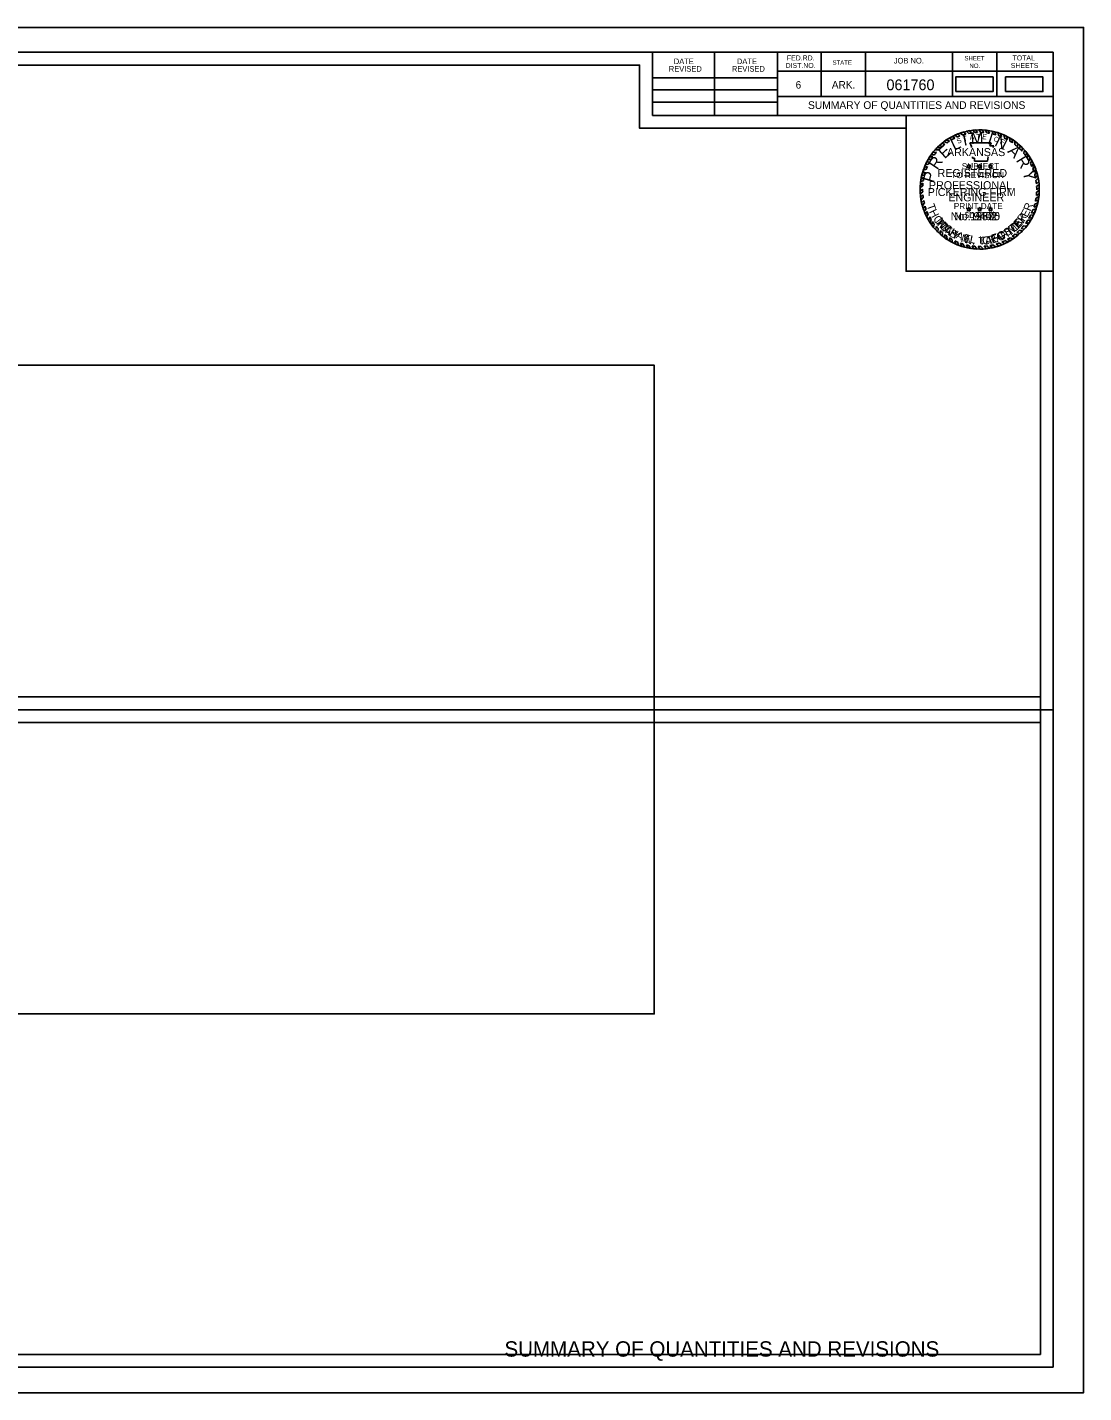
# Model space of a CAD drawing. Extents: x 365 to 1553, y -4 to 209.
# Drawn here: x 1387.5 to 1552.6, y -4 to 209.4 of the extents above; entities that cross this region are included whole.
import ezdxf

# ---------------------------------------------------------------- set-up
doc = ezdxf.new("R2010")
doc.units = 0
for name, color, linetype in [('Default', 7, 'Continuous'), ('R_Border', 7, 'Continuous'), ('R_Border Notes', 7, 'Continuous'), ('R_Border Plan-Plan', 7, 'Continuous'), ('R_Border Title', 7, 'Continuous'), ('R_No Plot', 7, 'Continuous'), ('STAMP_PE_CRAFTON', 7, 'Continuous'), ('STAMP_PE_FOSTER', 7, 'Continuous'), ('STAMP_PE_SEAL-INFO', 7, 'Continuous'), ('STAMP_PE_TAEGTMEYER', 7, 'Continuous'), ('STAMP_PE_TXT', 7, 'Continuous'), ('STAMP_PRELIMINARY', 7, 'Continuous')]:
    doc.layers.add(name, color=color, linetype=linetype)

msp = doc.modelspace()

# ---------------------------------------------------------------- linework, layer by layer
at = {"layer": 'Default'}
for points in [[(1532.59, 199.3), (1538.42, 199.3), (1538.42, 201.61), (1532.59, 201.61)], [(1540.36, 199.3), (1546.19, 199.3), (1546.19, 201.61), (1540.36, 201.61)], [(1315.56, 55.2), (1485.46, 55.2), (1485.46, 156.55), (1315.56, 156.55)]]:
    msp.add_lwpolyline(points, close=True, dxfattribs=at)
at = {"layer": 'R_Border'}
for p, q in [((1231.64, 205.46), (1547.82, 205.46)), ((1485.18, 195.58), (1485.18, 205.46)), ((1494.86, 195.58), (1494.86, 205.46)), ((1504.72, 205.46), (1504.72, 195.58)), ((1511.56, 205.46), (1511.56, 198.52)), ((1518.5, 205.46), (1518.5, 198.52)), ((1532.08, 205.46), (1532.08, 198.52)), ((1539.02, 205.46), (1539.02, 198.52)), ((1547.82, 0), (1547.82, 205.46)), ((1485.18, 201.44), (1504.72, 201.44)), ((1547.82, 202.52), (1504.72, 202.52)), ((1547.82, 202.54), (1547.82, 202.54)), ((1485.18, 199.58), (1504.72, 199.58)), ((1547.82, 198.52), (1504.72, 198.52)), ((1507.68, 198.52), (1547.82, 198.52)), ((1485.18, 197.64), (1504.72, 197.64)), ((1547.82, 195.58), (1485.18, 195.58)), ((1547.82, 0), (1231.64, 0))]:
    msp.add_line(p, q, dxfattribs=at)
at = {"layer": 'R_Border Plan-Plan'}
msp.add_line((1231.64, 102.73), (1547.82, 102.73), dxfattribs=at)
at = {"layer": 'R_No Plot'}
for points in [[(1219.23, 209.35), (1552.57, 209.35), (1552.57, -3.98), (1219.23, -3.98)], [(1545.82, 104.73), (1233.64, 104.73), (1233.64, 203.46), (1483.18, 203.46), (1483.18, 193.58), (1500.72, 193.58), (1524.82, 193.58), (1524.82, 171.25), (1545.82, 171.25)], [(1233.64, 203.46), (1483.18, 203.46), (1483.18, 193.58), (1500.72, 193.58), (1524.82, 193.58), (1524.82, 171.25), (1545.82, 171.25), (1545.82, 2), (1233.64, 2)], [(1524.82, 195.58), (1547.82, 195.58), (1547.82, 171.25), (1524.82, 171.25)], [(1233.64, 100.73), (1545.82, 100.73), (1545.82, 2), (1233.64, 2)]]:
    msp.add_lwpolyline(points, close=True, dxfattribs=at)
at = {"layer": 'STAMP_PE_SEAL-INFO'}
for p, q in [((1531.55, 192.03), (1531.98, 191.81)), ((1532, 192.28), (1532.46, 192.06)), ((1532.43, 192.49), (1532.82, 192.22)), ((1532.93, 192.71), (1533.23, 192.38)), ((1533.28, 192.84), (1533.66, 192.53)), ((1533.87, 193.02), (1534.16, 192.67)), ((1534.26, 193.11), (1534.62, 192.77)), ((1534.74, 193.21), (1535.04, 192.84)), ((1535.26, 193.28), (1535.54, 192.9)), ((1535.99, 192.93), (1535.68, 193.32)), ((1536.49, 192.93), (1536.21, 193.34)), ((1536.95, 192.91), (1536.69, 193.34)), ((1537.46, 192.86), (1537.16, 193.31)), ((1537.88, 192.8), (1537.62, 193.25)), ((1538.44, 192.68), (1538.27, 193.14)), ((1538.85, 192.57), (1538.69, 193.04)), ((1539.3, 192.42), (1539.16, 192.9)), ((1539.72, 192.26), (1539.57, 192.76)), ((1540.18, 192.06), (1540.07, 192.56)), ((1540.62, 191.83), (1540.54, 192.34)), ((1541.01, 191.6), (1540.97, 192.1)), ((1529.36, 190.22), (1529.88, 190.19)), ((1529.68, 190.57), (1530.23, 190.53)), ((1530.02, 190.89), (1530.48, 190.75)), ((1530.36, 191.19), (1530.89, 191.09)), ((1530.74, 191.52), (1531.2, 191.31)), ((1531.16, 191.79), (1531.6, 191.58)), ((1534.8, 191.31), (1538.14, 191.31)), ((1534.92, 191.01), (1534.8, 191.31)), ((1535.02, 190.71), (1534.92, 191.01)), ((1535.03, 190.59), (1535.02, 190.71)), ((1538.14, 191.31), (1537.91, 190.82)), ((1537.91, 190.82), (1538.55, 190.82)), ((1538.55, 190.82), (1538.4, 190.59)), ((1541.44, 191.32), (1541.41, 191.83)), ((1541.81, 191.05), (1541.84, 191.54)), ((1542.25, 190.68), (1542.27, 191.2)), ((1542.56, 190.39), (1542.63, 190.88)), ((1542.92, 190.01), (1542.99, 190.54)), ((1543.2, 189.7), (1543.33, 190.17)), ((1527.84, 187.89), (1528.34, 187.99)), ((1528.03, 188.27), (1528.52, 188.34)), ((1528.26, 188.7), (1528.75, 188.72)), ((1528.5, 189.1), (1529.02, 189.13)), ((1528.74, 189.44), (1529.24, 189.44)), ((1529.02, 189.81), (1529.56, 189.83)), ((1535.22, 188.89), (1535.19, 189.1)), ((1535.53, 188.89), (1535.22, 188.89)), ((1535.53, 188.46), (1535.53, 188.89)), ((1537.56, 188.46), (1535.53, 188.46)), ((1537.58, 188.79), (1537.56, 188.46)), ((1537.66, 189.1), (1537.58, 188.79)), ((1543.52, 189.28), (1543.66, 189.78)), ((1543.74, 188.96), (1543.92, 189.43)), ((1544.05, 188.47), (1544.23, 188.96)), ((1544.25, 188.1), (1544.48, 188.54)), ((1544.48, 187.62), (1544.71, 188.1)), ((1527.61, 185.89), (1527.14, 185.64)), ((1527.24, 186.14), (1527.71, 186.33)), ((1527.35, 186.54), (1527.82, 186.71)), ((1527.5, 187.05), (1527.99, 187.18)), ((1527.65, 187.45), (1528.16, 187.6)), ((1544.62, 187.28), (1544.88, 187.71)), ((1544.81, 186.73), (1545.09, 187.2)), ((1544.92, 186.37), (1545.22, 186.82)), ((1545.06, 185.81), (1545.37, 186.25)), ((1545.12, 185.43), (1545.48, 185.78)), ((1527.43, 184.57), (1527, 184.31)), ((1527.41, 184.08), (1527, 183.74)), ((1527.42, 183.67), (1527.02, 183.35)), ((1527.46, 185), (1527.03, 184.71)), ((1527.52, 185.43), (1527.08, 185.21)), ((1545.19, 184.92), (1545.56, 185.25)), ((1545.22, 184.5), (1545.61, 184.79)), ((1545.22, 183.58), (1545.64, 183.85)), ((1545.24, 183.98), (1545.64, 184.3)), ((1527.45, 183.18), (1527.08, 182.82)), ((1527.5, 182.75), (1527.15, 182.37)), ((1527.58, 182.29), (1527.24, 181.92)), ((1527.67, 181.87), (1527.36, 181.45)), ((1527.8, 181.42), (1527.5, 181)), ((1544.79, 181.24), (1545.28, 181.44)), ((1544.94, 181.73), (1545.41, 181.93)), ((1545.04, 182.18), (1545.5, 182.38)), ((1545.13, 182.68), (1545.58, 182.9)), ((1545.18, 183.07), (1545.62, 183.33)), ((1527.94, 181), (1527.66, 180.59)), ((1528.1, 180.57), (1527.84, 180.15)), ((1528.28, 180.19), (1528.05, 179.73)), ((1528.51, 179.73), (1528.32, 179.24)), ((1528.75, 179.33), (1528.56, 178.86)), ((1543.84, 179.23), (1544.31, 179.22)), ((1544.01, 179.51), (1544.51, 179.56)), ((1544.28, 180), (1544.77, 180.07)), ((1544.44, 180.34), (1544.93, 180.44)), ((1544.65, 180.86), (1545.14, 180.99)), ((1528.95, 179.01), (1528.84, 178.46)), ((1529.23, 178.62), (1529.13, 178.09)), ((1529.53, 178.25), (1529.45, 177.73)), ((1529.84, 177.91), (1529.77, 177.39)), ((1530.16, 177.58), (1530.13, 177.05)), ((1530.5, 177.27), (1530.5, 176.74)), ((1542.14, 177.27), (1542.61, 177.14)), ((1542.55, 177.64), (1542.99, 177.51)), ((1542.8, 177.9), (1543.28, 177.82)), ((1543.19, 178.34), (1543.65, 178.26)), ((1543.5, 178.73), (1544, 178.73)), ((1530.86, 176.98), (1530.88, 176.45)), ((1531.2, 176.73), (1531.24, 176.21)), ((1531.63, 176.45), (1531.69, 175.93)), ((1531.98, 176.24), (1532.07, 175.73)), ((1532.46, 175.99), (1532.62, 175.47)), ((1532.83, 175.82), (1533.01, 175.31)), ((1533.32, 175.63), (1533.53, 175.13)), ((1533.73, 175.49), (1533.96, 175)), ((1534.24, 175.36), (1534.45, 174.89)), ((1534.64, 175.27), (1534.89, 174.81)), ((1535.14, 175.19), (1535.38, 174.75)), ((1535.58, 175.14), (1535.85, 174.71)), ((1536.06, 175.11), (1536.36, 174.7)), ((1536.52, 175.11), (1536.86, 174.72)), ((1537.04, 175.14), (1537.37, 174.76)), ((1537.48, 175.18), (1537.85, 174.83)), ((1537.92, 175.25), (1538.31, 174.91)), ((1538.42, 175.36), (1538.79, 175.03)), ((1538.88, 175.48), (1539.29, 175.19)), ((1539.37, 175.65), (1539.81, 175.38)), ((1539.79, 175.81), (1540.21, 175.55)), ((1540.25, 176.02), (1540.73, 175.81)), ((1540.65, 176.23), (1541.07, 176)), ((1541.07, 176.48), (1541.52, 176.28)), ((1541.41, 176.71), (1541.85, 176.52)), ((1541.87, 177.05), (1542.34, 176.9))]:
    msp.add_line(p, q, dxfattribs=at)
for radius, start, end in [(9.32, 117.6544, 120.8099), (8.91, 115.6869, 119.1583), (9.32, 111.3124, 114.7026), (8.91, 110.3086, 113.1659), (9.32, 105.2339, 109.0352), (8.91, 104.0352, 107.3615), (9.32, 99.7525, 102.7765), (8.91, 98.258, 101.0329), (9.32, 93.9381, 96.5517), (8.91, 92.1102, 95.0367), (9.32, 87.7298, 90.6707), (8.91, 85.9628, 88.9097), (9.32, 81.9732, 84.8236), (8.91, 79.9264, 82.696), (9.32, 75.3125, 77.9426), (8.91, 73.5575, 76.2314), (9.32, 69.6061, 72.3058), (8.91, 67.6248, 70.504), (9.32, 63.1329, 66.2704), (8.91, 61.1558, 64.3784), (9.32, 56.9003, 60.0942), (9.32, 135.4021, 138.3031), (8.91, 133.1331, 136.2562), (9.32, 129.7326, 132.5376), (8.91, 127.5297, 130.9683), (9.32, 123.6199, 126.5906), (8.91, 121.9746, 125.11), (8.91, 54.9238, 58.2702), (8.91, 48.3016, 52.0395), (9.32, 50.3492, 53.7159), (8.91, 42.2212, 45.5512), (9.32, 44.3405, 47.3929), (9.32, 38.1247, 41.2316), (9.32, 152.864, 155.5189), (9.32, 147.0072, 149.899), (8.91, 151.0315, 153.573), (9.32, 141.6056, 144.4486), (8.91, 145.0197, 148.2104), (8.91, 139.301, 142.5873), (8.91, 36.135, 39.5311), (8.91, 29.9032, 33.6645), (9.32, 31.9614, 35.4294), (8.91, 23.7732, 27.2211), (9.32, 25.9391, 29.0125), (9.32, 170.0003, 172.6878), (9.32, 164.3068, 166.894), (9.32, 158.4077, 161.0701), (8.91, 167.9048, 170.9039), (8.91, 162.4331, 165.0013), (8.91, 156.3402, 159.2319), (8.91, 17.6802, 21.4251), (9.32, 19.9538, 23.3141), (8.91, 11.5444, 15.2364), (9.32, 13.8421, 17.4447), (9.32, 7.5852, 10.8621), (9.32, 175.7409, 178.2066), (9.32, 181.7251, 184.1626), (8.91, 179.6454, 182.2633), (8.91, 173.73, 176.4734), (8.91, 5.7599, 9.0606), (8.91, 353.8632, 357.1274), (8.91, 359.7329, 3.0639), (9.32, 1.7215, 4.7268), (9.32, 355.7156, 358.9569), (9.32, 187.4204, 190.1927), (9.32, 193.0369, 195.9973), (8.91, 185.4539, 188.234), (8.91, 191.2274, 193.9858), (8.91, 196.9675, 199.8353), (8.91, 341.777, 345.0925), (8.91, 348.0778, 351.3435), (9.32, 343.8925, 347.035), (9.32, 349.8305, 353.0885), (9.32, 198.8967, 201.6281), (9.32, 204.5479, 207.4328), (8.91, 202.7761, 205.4791), (9.32, 210.8636, 213.6571), (8.91, 208.7883, 211.7934), (8.91, 323.5851, 327.4407), (9.32, 325.4405, 328.9872), (8.91, 329.5549, 333.2076), (8.91, 335.6038, 339.1858), (9.32, 331.4037, 334.9332), (9.32, 337.3837, 340.9933), (9.32, 216.6115, 219.491), (8.91, 214.1838, 217.2747), (9.32, 222.48, 225.3801), (8.91, 220.3909, 223.3056), (8.91, 226.2494, 229.2407), (8.91, 310.7744, 314.3161), (9.32, 312.4518, 315.6633), (8.91, 316.6531, 320.3711), (9.32, 318.2846, 321.8043), (9.32, 228.3665, 231.348), (8.91, 232.229, 234.9336), (9.32, 234.295, 236.9452), (8.91, 238.2223, 240.8353), (9.32, 240.1977, 242.8613), (8.91, 244.3204, 246.9486), (9.32, 246.576, 249.1558), (8.91, 250.3491, 253.1216), (9.32, 252.5967, 255.3252), (8.91, 256.505, 259.1192), (8.91, 262.3783, 265.2012), (8.91, 268.3215, 271.277), (8.91, 274.6157, 277.4486), (8.91, 280.3459, 283.5814), (9.32, 282.3199, 285.3702), (8.91, 286.6423, 289.9783), (9.32, 288.5709, 291.9733), (8.91, 292.8745, 296.1185), (9.32, 294.6481, 298.2166), (8.91, 299.0768, 302.1724), (9.32, 300.621, 303.8703), (8.91, 304.823, 308.5143), (9.32, 306.3721, 310.208), (9.32, 258.4433, 261.1398), (9.32, 264.1978, 267.1009), (9.32, 270.2548, 273.3361), (9.32, 276.4239, 279.4357)]:
    msp.add_arc((1536.32, 184.02), radius, start, end, dxfattribs=at)
at = {"layer": 'STAMP_PE_TXT'}
for p, q in [((1534.5, 187.59), (1534.3, 187.74)), ((1534.3, 187.74), (1534.55, 187.74)), ((1534.55, 187.74), (1534.62, 187.97)), ((1534.62, 187.97), (1534.7, 187.74)), ((1534.7, 187.74), (1534.95, 187.74)), ((1534.95, 187.74), (1534.75, 187.59)), ((1536.2, 187.59), (1536, 187.74)), ((1536, 187.74), (1536.25, 187.74)), ((1536.25, 187.74), (1536.32, 187.97)), ((1536.32, 187.97), (1536.4, 187.74)), ((1536.4, 187.74), (1536.64, 187.74)), ((1536.64, 187.74), (1536.45, 187.59)), ((1537.9, 187.59), (1537.7, 187.74)), ((1537.7, 187.74), (1537.94, 187.74)), ((1537.94, 187.74), (1538.02, 187.97)), ((1538.02, 187.97), (1538.1, 187.74)), ((1538.1, 187.74), (1538.34, 187.74)), ((1538.34, 187.74), (1538.14, 187.59)), ((1534.43, 187.36), (1534.5, 187.59)), ((1534.62, 187.5), (1534.43, 187.36)), ((1534.82, 187.36), (1534.62, 187.5)), ((1534.75, 187.59), (1534.82, 187.36)), ((1536.12, 187.36), (1536.2, 187.59)), ((1536.32, 187.5), (1536.12, 187.36)), ((1536.52, 187.36), (1536.32, 187.5)), ((1536.45, 187.59), (1536.52, 187.36)), ((1537.82, 187.36), (1537.9, 187.59)), ((1538.02, 187.5), (1537.82, 187.36)), ((1538.22, 187.36), (1538.02, 187.5)), ((1538.14, 187.59), (1538.22, 187.36)), ((1534.5, 180.89), (1534.3, 181.03)), ((1534.3, 181.03), (1534.55, 181.03)), ((1534.43, 180.65), (1534.5, 180.89)), ((1534.62, 180.8), (1534.43, 180.65)), ((1534.55, 181.03), (1534.62, 181.26)), ((1534.62, 181.26), (1534.7, 181.03)), ((1534.82, 180.65), (1534.62, 180.8)), ((1534.7, 181.03), (1534.95, 181.03)), ((1534.95, 181.03), (1534.75, 180.89)), ((1534.75, 180.89), (1534.82, 180.65)), ((1536.2, 180.89), (1536, 181.03)), ((1536, 181.03), (1536.25, 181.03)), ((1536.12, 180.65), (1536.2, 180.89)), ((1536.32, 180.8), (1536.12, 180.65)), ((1536.25, 181.03), (1536.32, 181.26)), ((1536.32, 181.26), (1536.4, 181.03)), ((1536.52, 180.65), (1536.32, 180.8)), ((1536.4, 181.03), (1536.64, 181.03)), ((1536.64, 181.03), (1536.45, 180.89)), ((1536.45, 180.89), (1536.52, 180.65)), ((1537.9, 180.89), (1537.7, 181.03)), ((1537.7, 181.03), (1537.94, 181.03)), ((1537.82, 180.65), (1537.9, 180.89)), ((1538.02, 180.8), (1537.82, 180.65)), ((1537.94, 181.03), (1538.02, 181.26)), ((1538.02, 181.26), (1538.1, 181.03)), ((1538.22, 180.65), (1538.02, 180.8)), ((1538.1, 181.03), (1538.34, 181.03)), ((1538.34, 181.03), (1538.14, 180.89)), ((1538.14, 180.89), (1538.22, 180.65))]:
    msp.add_line(p, q, dxfattribs=at)
at = {"layer": 'STAMP_PRELIMINARY'}
msp.add_circle((1536.32, 184.02), 9.32, dxfattribs=at)

# ---------------------------------------------------------------- texts
at = {"layer": 'R_Border'}
for s, height, p in [('FED.RD.', 0.782, (1506.2, 204.18)), ('SHEET', 0.684, (1533.94, 204.18)), ('TOTAL', 0.782, (1541.46, 204.18)), ('REVISED', 0.879, (1487.74, 202.42)), ('DATE', 0.879, (1488.52, 203.6)), ('REVISED', 0.879, (1497.6, 202.42)), ('DATE', 0.879, (1498.38, 203.6)), ('DIST.NO.', 0.782, (1506, 203)), ('STATE', 0.684, (1513.32, 203.5)), ('JOB NO.', 0.879, (1522.9, 203.7)), ('NO.', 0.684, (1534.72, 203)), ('SHEETS', 0.782, (1541.18, 203)), ('6', 1.17, (1507.56, 199.78)), ('ARK.', 1.172, (1513.22, 199.78))]:
    msp.add_text(s, height=height, dxfattribs=at).set_placement(p)
at = {"layer": 'R_Border Notes'}
for s, height, p in [('061760', 1.68, (1521.76, 199.53)), ('SUMMARY OF QUANTITIES AND REVISIONS', 1.2, (1509.49, 196.6))]:
    msp.add_text(s, height=height, dxfattribs=at).set_placement(p)
at = {"layer": 'R_Border Title'}
msp.add_text('SUMMARY OF QUANTITIES AND REVISIONS', height=2.4, dxfattribs=at).set_placement((1462.06, 1.65))
at = {"layer": 'STAMP_PE_CRAFTON'}
for s, rotation, p in [('T', 310.7442, (1529.29, 178.92)), ('N', 49.2411, (1542.6, 178.04)), ('O', 317.6422, (1529.96, 178.11)), ('N', 324.4537, (1530.8, 177.32)), ('Y', 331.1686, (1531.83, 176.61)), ('A', 20.5125, (1539, 175.78)), ('F', 28.7821, (1539.98, 176.15)), ('T', 34.1136, (1540.9, 176.66)), ('O', 41.8391, (1541.76, 177.26)), ('N', 347.4752, (1533.89, 175.69)), ('.', 356.8926, (1535.12, 175.41)), ('C', 6.0117, (1536.79, 175.36)), ('R', 14.8189, (1537.89, 175.48))]:
    msp.add_text(s, height=1.25, rotation=rotation, dxfattribs=at).set_placement(p)
msp.add_text('No. 12370', height=1.25, dxfattribs=at).set_placement((1531.78, 179.22))
at = {"layer": 'STAMP_PE_FOSTER'}
for s, rotation, p in [('M', 308.339, (1529.44, 179.04)), ('E', 46.9613, (1542.32, 178.01)), ('R', 54.5031, (1543.05, 178.83)), ('I', 314.1842, (1530.24, 178.11)), ('C', 319.8733, (1530.59, 177.75)), ('H', 327.7235, (1531.52, 177.02)), ('A', 335.7276, (1532.5, 176.44)), ('E', 343.5779, (1533.64, 175.97)), ('F', 15.8691, (1538.36, 175.78)), ('O', 23.719, (1539.4, 176.1)), ('S', 31.7234, (1540.51, 176.63)), ('T', 39.4194, (1541.46, 177.26)), ('L', 350.8115, (1534.7, 175.69)), ('L', 1.2666, (1536.24, 175.53)), ('.', 6.8035, (1537.28, 175.59))]:
    msp.add_text(s, height=1.2, rotation=rotation, dxfattribs=at).set_placement(p)
msp.add_text('No. 9402', height=1.25, dxfattribs=at).set_placement((1532.31, 179.22))
at = {"layer": 'STAMP_PE_TAEGTMEYER'}
for s, rotation, p in [('T', 289.646, (1528.02, 181.53)), ('R', 69.57, (1544.27, 180.54)), ('H', 296.7339, (1528.38, 180.55)), ('O', 303.7708, (1528.97, 179.44)), ('M', 314.2033, (1529.62, 178.49)), ('E', 46.8094, (1542.36, 177.8)), ('Y', 53.9986, (1543.1, 178.61)), ('E', 63.0984, (1543.77, 179.56)), ('A', 321.0594, (1530.59, 177.52)), ('S', 327.8239, (1531.41, 176.88)), ('G', 23.3052, (1539.32, 175.88)), ('T', 31.466, (1540.42, 176.38)), ('M', 39.3, (1541.32, 176.92)), ('N', 344.2727, (1533.31, 175.87)), ('.', 350.6464, (1534.52, 175.54)), ('T', 3.0061, (1536.19, 175.34)), ('A', 8.9826, (1537.23, 175.4)), ('E', 17.6836, (1538.27, 175.55))]:
    msp.add_text(s, height=1.25, rotation=rotation, dxfattribs=at).set_placement(p)
msp.add_text('No. 19605', height=1.25, dxfattribs=at).set_placement((1531.78, 179.22))
at = {"layer": 'STAMP_PE_TXT'}
for s, rotation, p in [('S', 23.5541, (1532.92, 191.13)), ('T', 16.311, (1533.84, 191.5)), ('A', 9.0679, (1534.81, 191.75)), ('T', 1.8248, (1535.79, 191.88)), ('E', 355.2002, (1536.7, 191.89)), ('O', 342.2506, (1538.43, 191.61)), ('F', 335.0075, (1539.4, 191.27))]:
    msp.add_text(s, height=0.781, rotation=rotation, dxfattribs=at).set_placement(p)
for s, p in [('ARKANSAS', (1531.21, 189.23)), ('REGISTERED', (1529.74, 185.96)), ('PROFESSIONAL', (1528.39, 184.06)), ('ENGINEER', (1531.43, 182.16))]:
    msp.add_text(s, height=1.25, dxfattribs=at).set_placement(p)
at = {"layer": 'STAMP_PRELIMINARY'}
for s, rotation, p in [('I', 12.5248, (1533.86, 190.81)), ('M', 3.1074, (1534.96, 191.12)), ('I', 342.3164, (1537.43, 191.19)), ('N', 333.9382, (1538.53, 190.91)), ('E', 42.3578, (1530.85, 188.72)), ('L', 25.513, (1532.33, 190.05)), ('A', 315.6579, (1540.57, 189.89)), ('R', 56.2292, (1529.69, 186.99)), ('R', 301.3831, (1541.94, 188.57)), ('P', 73.913, (1529.14, 184.96)), ('Y', 283.2593, (1543.02, 186.79))]:
    msp.add_text(s, height=1.8, rotation=rotation, dxfattribs=at).set_placement(p)
for s, height, p in [('SUBJECT', 0.96, (1533.52, 187.17)), ('TO REVISION', 0.96, (1531.86, 185.79)), ('PICKERING FIRM', 1.25, (1528.2, 182.99)), ('PRINT DATE', 0.96, (1532.28, 180.94)), ('$DATE$', 0.96, (1533.96, 179.55))]:
    msp.add_text(s, height=height, dxfattribs=at).set_placement(p)

doc.saveas('drawing.dxf')
